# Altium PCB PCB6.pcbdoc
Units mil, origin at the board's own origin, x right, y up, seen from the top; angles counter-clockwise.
Board outline 8325 x 8105 mil, 2 copper layers (Top Layer, Bottom Layer); 35 components, 41 nets, 138 pads, 0 vias.
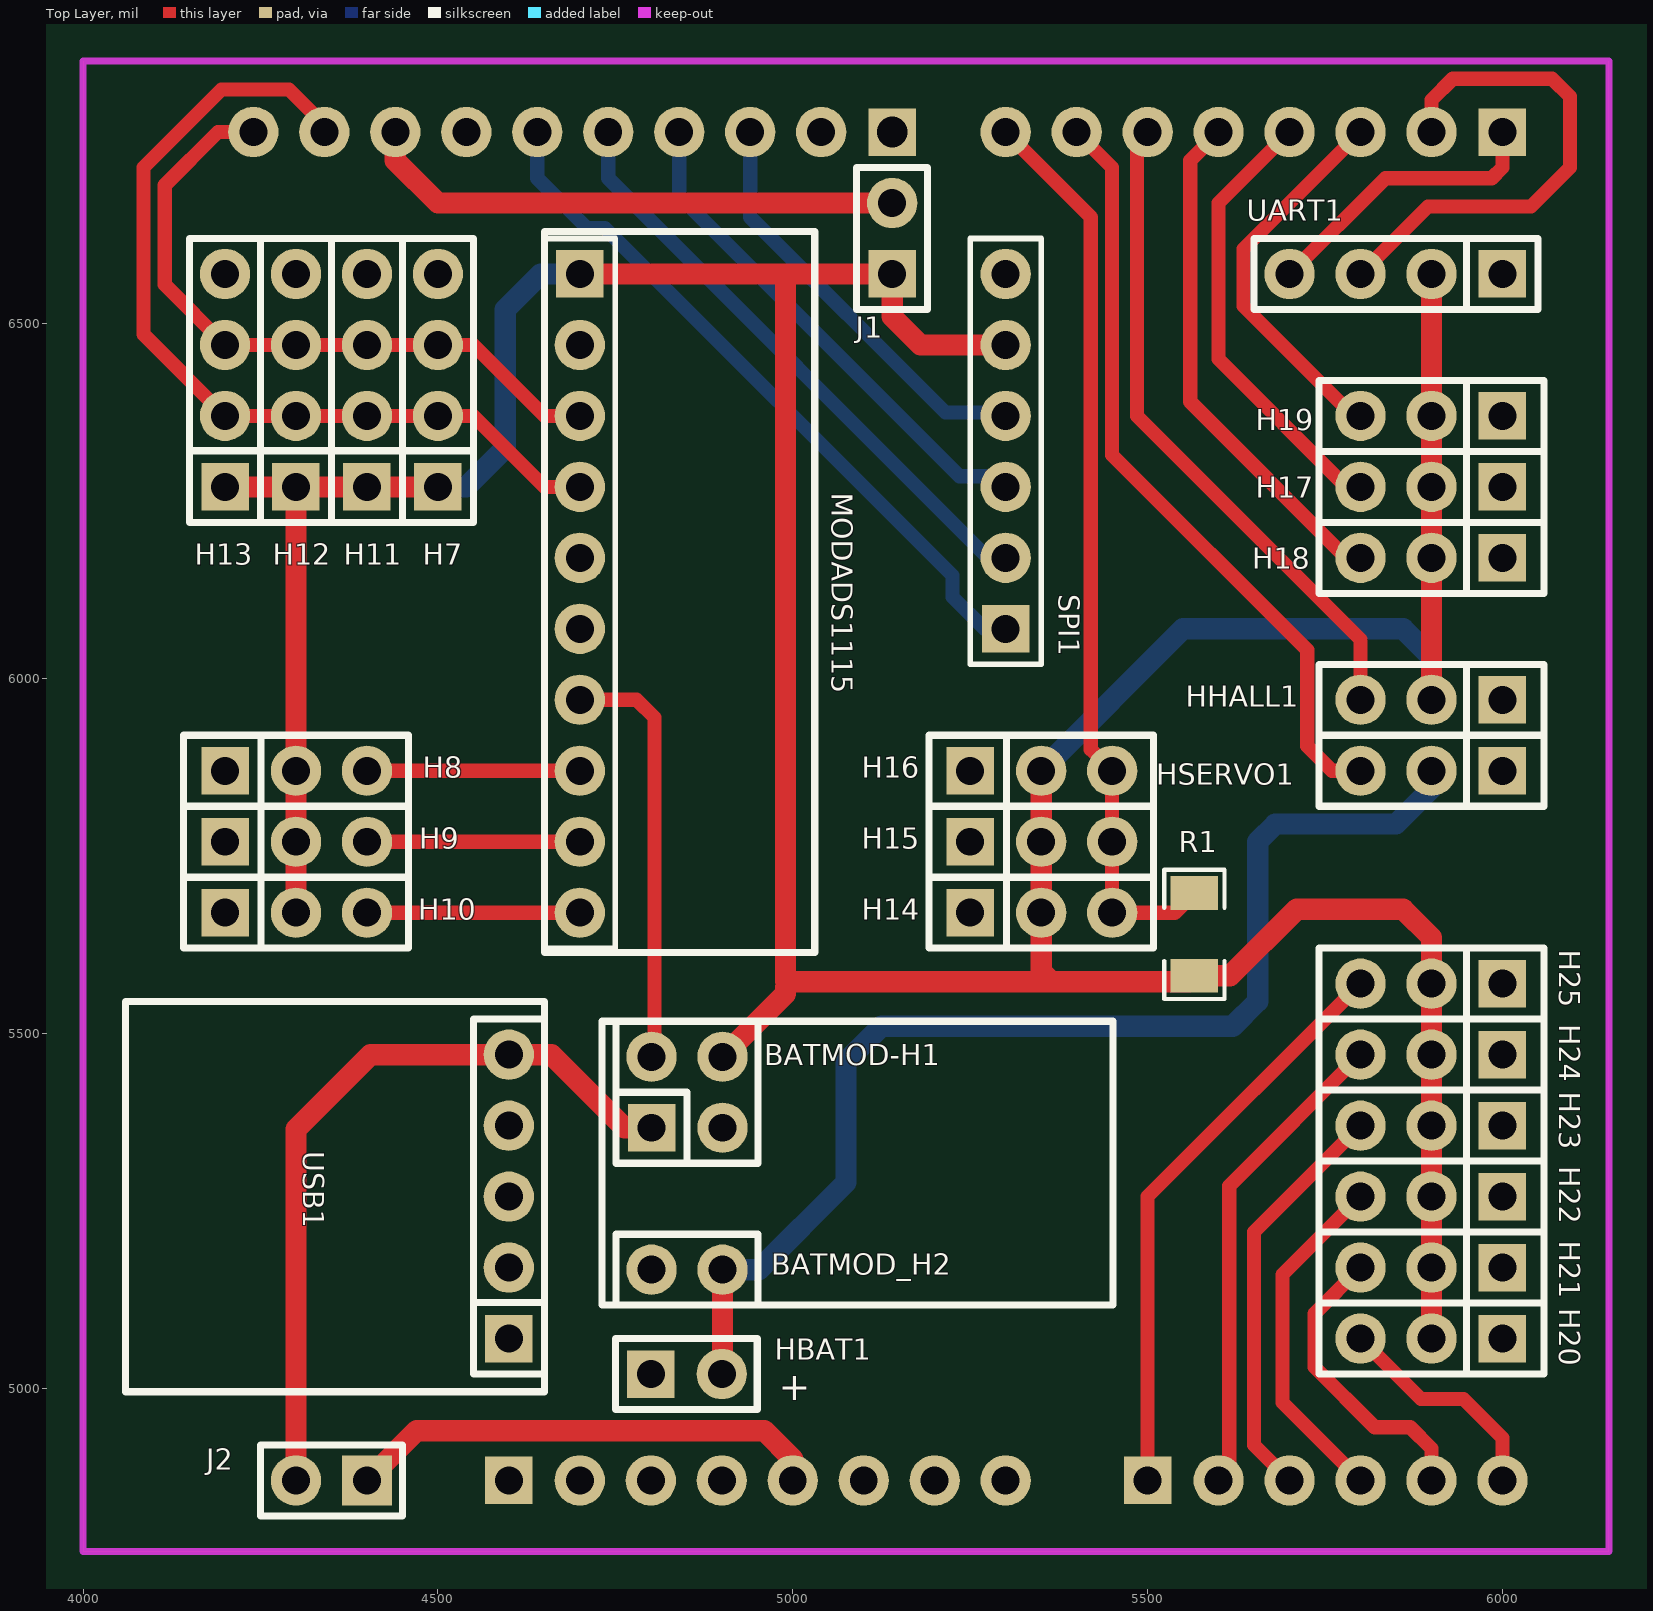
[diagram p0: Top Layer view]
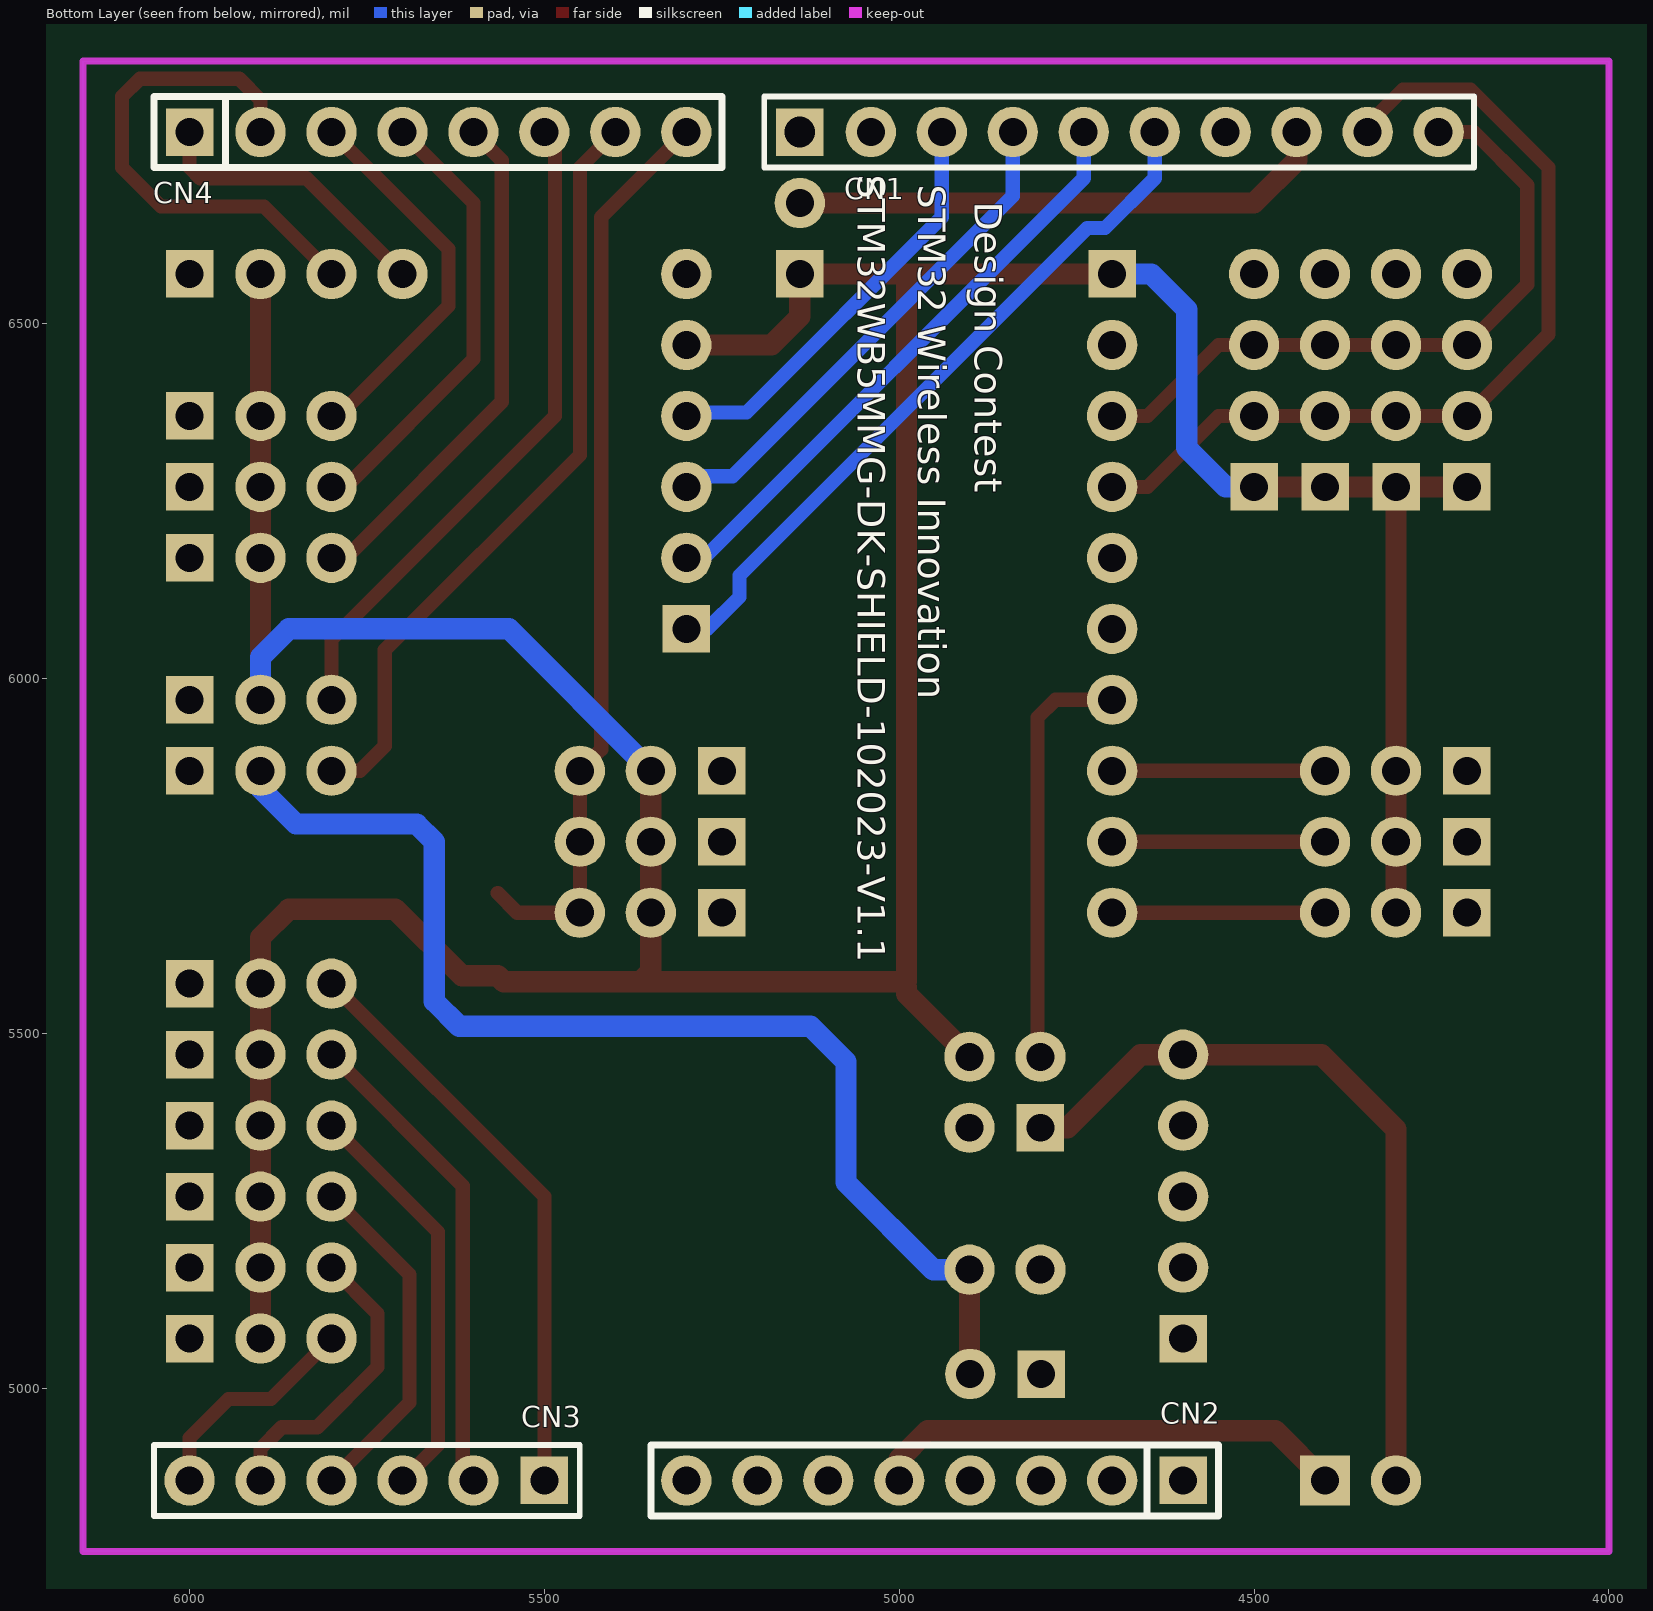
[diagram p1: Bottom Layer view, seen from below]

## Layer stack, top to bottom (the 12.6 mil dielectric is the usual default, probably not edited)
Top Layer: signal copper (thickness not stored)
Dielectric: dielectric 12.6, FR-4, Dk 4.8
Bottom Layer: signal copper (thickness not stored)

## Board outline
11075,2750 2750,2750 2750,10855 11075,10855

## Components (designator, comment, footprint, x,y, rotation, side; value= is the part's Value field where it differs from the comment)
BATMOD-H1 "HDR-M_2.54_2x2" hdr-th_4p-p2.54-v-m-r2-c2-s2.54-1 4851,5417 r0 top
BATMOD_H2 "HDR-M_2.54_1x2P" hdr-th_2p-p2.54-v-m-1#1 4851,5167 r0 top
CN1 "HDR-M_2.54_1x10P" hdr-th_10p-p2.54-v-m-1#1 4690,6770 r180 bottom
CN2 "HDR-M_2.54_1x8P" hdr-th_8p-p2.54-v-m#1 4950,4870 r0 bottom
CN3 "HDR-M_2.54_1x6P" hdr-th_6p-p2.54-v-m-1#1 5750,4870 r0 bottom
CN4 "HDR-M_2.54_1x8P" hdr-th_8p-p2.54-v-m#2 5650,6770 r180 bottom
H7 "HDR-M_2.54_1x4P" hdr-th_4p-p2.54-v-m 4500,6420 r90 top
H8 "HDR-M_2.54_1x3P" hdr-th_3p-p2.54-v-m#1 4300,5870 r0 top
H9 "HDR-M_2.54_1x3P" hdr-th_3p-p2.54-v-m#1 4300,5770 r0 top
H10 "HDR-M_2.54_1x3P" hdr-th_3p-p2.54-v-m#1 4300,5670 r0 top
H11 "HDR-M_2.54_1x4P" hdr-th_4p-p2.54-v-m 4400,6420 r90 top
H12 "HDR-M_2.54_1x4P" hdr-th_4p-p2.54-v-m 4300,6420 r90 top
H13 "HDR-M_2.54_1x4P" hdr-th_4p-p2.54-v-m 4200,6420 r90 top
H14 "HDR-M_2.54_1x3P" hdr-th_3p-p2.54-v-m#1 5350,5670 r0 top
H15 "HDR-M_2.54_1x3P" hdr-th_3p-p2.54-v-m#1 5350,5770 r0 top
H16 "HDR-M_2.54_1x3P" hdr-th_3p-p2.54-v-m#1 5350,5870 r0 top
H17 "HDR-M_2.54_1x3P" hdr-th_3p-p2.54-v-m#1 5900,6270 r180 top
H18 "HDR-M_2.54_1x3P" hdr-th_3p-p2.54-v-m#1 5900,6170 r180 top
H19 "HDR-M_2.54_1x3P" hdr-th_3p-p2.54-v-m#1 5900,6370 r180 top
H20 "HDR-M_2.54_1x3P" hdr-th_3p-p2.54-v-m#1 5900,5070 r180 top
H21 "HDR-M_2.54_1x3P" hdr-th_3p-p2.54-v-m#2 5900,5170 r180 top
H22 "HDR-M_2.54_1x3P" hdr-th_3p-p2.54-v-m#2 5900,5270 r180 top
H23 "HDR-M_2.54_1x3P" hdr-th_3p-p2.54-v-m#2 5900,5370 r180 top
H24 "HDR-M_2.54_1x3P" hdr-th_3p-p2.54-v-m#2 5900,5470 r180 top
H25 "HDR-M_2.54_1x3P" hdr-th_3p-p2.54-v-m#2 5900,5570 r180 top
HBAT1 "HDR-M_2.54_1x2P" hdr-th_2p-p2.54-v-m-1#2 4850,5020 r0 top
HHALL1 "HDR-M_2.54_1x3P" hdr-th_3p-p2.54-v-m#1 5900,5970 r180 top
HSERVO1 "HDR-M_2.54_1x3P" hdr-th_3p-p2.54-v-m#1 5900,5870 r180 top
J1 "HDR-M_2.54_1x2P" hdr-th_2p-p2.54-v-m-1#2 5140,6620 r90 top
J2 "HDR-M_2.54_1x2P" HDR-TH_2P-P2.54-V-M-1 4350,4870 r180 top
MODADS1115 "HDR-M_2.54_1x10P" hdr-th_10p-p2.54-v-m-1#2 4700,6120 r270 top
R1 "Res_1206" R1206 5565.77,5639.45 r270 top
SPI1 "HDR-M_2.54_1x6P" hdr-th_6p-p2.54-v-m-1#2 5300,6320 r90 top
UART1 "HDR-M_2.54_1x4P" hdr-th_4p-p2.54-v-m 5850,6570 r180 top
USB1 "HDR-M_2.54_1x5P" hdr-th_5p-p2.54-v-m 4600,5270 r90 top

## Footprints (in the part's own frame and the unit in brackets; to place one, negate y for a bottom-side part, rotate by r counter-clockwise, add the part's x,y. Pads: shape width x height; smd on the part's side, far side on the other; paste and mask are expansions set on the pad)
hdr-th_2p-p2.54-v-m-1#1 [mil]
  round 70.9 hole 39.4: 1(-50,0) 2(50,0)
  silkscreen extent -100,-50 100,50
hdr-th_2p-p2.54-v-m-1#2 [mil]
  rect 66.9x66.9 hole 39.4: 1(-50,0)
  round 70.9 hole 39.4: 2(50,0)
  silkscreen extent -100,-50 100,50
HDR-TH_2P-P2.54-V-M-1 [mm]
  rect 1.8x1.8 hole 1: 1(-1.27,0)
  round 1.8 hole 1: 2(1.27,0)
  silkscreen extent -2.54,-1.27 2.54,1.27
hdr-th_3p-p2.54-v-m#1 [mil]
  rect 66.9x66.9 hole 39.4: 1(-100,0)
  round 70.9 hole 39.4: 2(0,0) 3(100,0)
  silkscreen extent -158,-50 158,50
hdr-th_3p-p2.54-v-m#2 [mil]
  rect 66.93x66.93 hole 39.4: 1(-100,0)
  round 70.9 hole 39.4: 2(0,0) 3(100,0)
  silkscreen extent -158,-50 158,50
hdr-th_4p-p2.54-v-m [mil]
  rect 66.9x66.9 hole 39.4: 1(-150,0)
  round 70.9 hole 39.4: 2(-50,0) 3(50,0) 4(150,0)
  silkscreen extent -200,-50 200,50
hdr-th_4p-p2.54-v-m-r2-c2-s2.54-1 [mil]
  rect 66.9x66.9 hole 39.4: 1(-50,-50)
  round 70.9 hole 39.4: 2(-50,50) 3(50,-50) 4(50,50)
  silkscreen extent -100,-100 100,100
hdr-th_5p-p2.54-v-m [mil]
  rect 66.9x66.9 hole 39.4: 1(-200,0)
  round 70.9 hole 39.4: 2(-100,0) 3(0,0) 4(100,0) 5(200,0)
  silkscreen extent -250,-50 250,50
hdr-th_6p-p2.54-v-m-1#1 [mm]
  rect 1.699x1.699 hole 1.001: 1(-6.35,0)
  round 1.8 hole 1.001: 2(-3.81,0) 3(-1.27,0) 4(1.27,0) 5(3.81,0) 6(6.35,0)
  silkscreen extent -7.62,-1.27 7.62,1.27
hdr-th_6p-p2.54-v-m-1#2 [mm]
  rect 1.699x1.699 hole 1.001: 1(-6.35,0)
  round 1.801 hole 1.001: 2(-3.81,0) 3(-1.27,0) 4(1.27,0) 5(3.81,0) 6(6.35,0)
  silkscreen extent -7.62,-1.27 7.62,1.27
hdr-th_8p-p2.54-v-m#1 [mm]
  rect 1.699x1.699 hole 1.001: 1(-8.89,0)
  round 1.801 hole 1: 2(-6.35,0) 3(-3.81,0) 4(-1.27,0) 5(1.27,0) 6(3.81,0) 7(6.35,0) 8(8.89,0)
  silkscreen extent -10.16,-1.27 10.16,1.27
hdr-th_8p-p2.54-v-m#2 [mm]
  rect 1.699x1.699 hole 1: 1(-8.89,0)
  round 1.801 hole 1: 2(-6.35,0) 3(-3.81,0) 4(-1.27,0) 5(1.27,0) 6(3.81,0) 7(6.35,0) 8(8.89,0)
  silkscreen extent -10.16,-1.27 10.16,1.27
hdr-th_10p-p2.54-v-m-1#1 [mm]
  rect 1.699x1.7 hole 1.1: 1(-11.43,0)
  round 1.801 hole 1.001: 2(-8.89,0) 3(-6.35,0) 4(-3.81,0) 5(-1.27,0) 6(1.27,0) 7(3.81,0) 8(6.35,0) 9(8.89,0) 10(11.43,0)
  silkscreen extent -12.7,-1.27 12.7,1.27
hdr-th_10p-p2.54-v-m-1#2 [mm]
  rect 1.699x1.699 hole 1.001: 1(-11.43,0)
  round 1.801 hole 1.001: 2(-8.89,0) 3(-6.35,0) 4(-3.81,0) 5(-1.27,0) 6(1.27,0) 7(3.81,0) 8(6.35,0) 9(8.89,0) 10(11.43,0)
  silkscreen extent -12.7,-1.27 12.7,1.27
R1206 [mil]
  rect 47.54x66.97 smd: 1(-58.22,0) 2(58.22,0)
  silkscreen extent -91,-42 91,42

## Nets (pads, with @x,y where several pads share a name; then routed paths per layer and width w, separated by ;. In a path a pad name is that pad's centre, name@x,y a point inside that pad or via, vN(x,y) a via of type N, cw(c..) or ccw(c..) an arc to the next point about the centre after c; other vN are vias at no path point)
3V3: BATMOD-H1.4 H7.1 H8.2 H9.2 H10.2 H11.1 H12.1 H13.1 H14.2 H15.2 H16.2 H17.2 H18.2 H19.2 H20.2 H21.2 H22.2 H23.2 H24.2 H25.2 HHALL1.2 J1.1 MODADS1115.1 R1.2 SPI1.5 UART1.2 | length 6296.7
  Top Layer w30: H13.1 H12.1 ; H10.2 H9.2 H8.2 H12.1 ; H7.1 H11.1 H12.1 ; MODADS1115.1 4989.89,6570 ; BATMOD-H1.4 4989.89,5555.89 4989.89,5564.89 ; SPI1.5 5180,6470 5140,6510 J1.1 4989.89,6570 ; H16.2 H15.2 H14.2 5350,5586.99 5364.33,5572.67 ; H20.2 H21.2 H22.2 H23.2 H24.2 H25.2 5900,5635 5860,5675 5710,5675 5616.23,5581.23 R1.2 5557.21,5572.67 5364.33,5572.67 ; HHALL1.2 H18.2 H17.2 H19.2 UART1.2 ; 4989.89,6570 4989.89,5573 4993.95,5568.95 4997.67,5572.67 5364.33,5572.67
  Bottom Layer w30: H7.1 4540,6270 4595,6325 4595,6520 4645,6570 MODADS1115.1 ; H16.2 5550,6070 5860,6070 5900,6030 HHALL1.2
5V: CN2.5 J2.1 | length 675.6
  Top Layer w30: J2.1 4470,4940 4960,4940 5000,4900 CN2.5
AIN1: H8.3 MODADS1115.8 | length 300
  Top Layer w20: H8.3 MODADS1115.8
AIN2: H9.3 MODADS1115.9 | length 300
  Top Layer w20: H9.3 MODADS1115.9
AIN3: H10.3 MODADS1115.10 | length 300
  Top Layer w20: H10.3 MODADS1115.10
ALERT: MODADS1115.6
AVDD: CN1.8 J1.2 | length 764.9
  Top Layer w30: CN1.8 4440,6730 4500,6670 J1.2
D+: USB1.3
D-: USB1.4
GND: BATMOD-H1.3 BATMOD_H2.1 CN1.7 CN2.6 CN2.7 H7.4 H8.1 H9.1 H10.1 H11.4 H12.4 H13.4 H14.1 H15.1 H16.1 H17.1 H18.1 H19.1 H20.1 H21.1 H22.1 H23.1 H24.1 H25.1 HBAT1.1 HHALL1.1 HSERVO1.1 MODADS1115.2 MODADS1115.5 SPI1.6 UART1.1 USB1.1
IO: USB1.2
IOREF: CN2.2
NRST: CN2.3
PA1_SPI1_SCK: CN1.6 SPI1.1 | length 1005.6
  Bottom Layer w20: CN1.6 4640,6705 4710,6635 4735,6635 5225,6145 5225,6115 5270,6070 SPI1.1
PA2: CN3.2 H24.3 | length 682.8
  Top Layer w20: CN3.2 5615,4885 5615,5285 H24.3
PA4_SPI1_NSS: CN1.3 SPI1.4 | length 596
  Bottom Layer w20: CN1.3 4940,6650 5215,6375 5295,6375 SPI1.4
PA5: CN3.3 H23.3 | length 582.8
  Top Layer w20: CN3.3 5650,4920 5650,5220 H23.3
PA7_SPI1_MOSI/TIM17_CH1: CN1.4 SPI1.3 | length 719.8
  Bottom Layer w20: CN1.4 4840,6680 5235,6285 5285,6285 SPI1.3
PA10_I2C1_SDA: CN1.9 H7.2 H11.2 H12.2 H13.2 MODADS1115.4 | length 1270.3
  Top Layer w20: CN1.9 4340,6780 4290,6830 4195,6830 4085,6720 4085,6485 H13.2 H12.2 H11.2 H7.2 4550,6370 4650,6270 MODADS1115.4
PB2/ONEWIRE: CN4.8 H14.3 H15.3 H16.3 R1.1 | length 1289.4
  Top Layer w20: CN4.8 5420,6650 5420,5900 H16.3 H15.3 H14.3 5538.1,5670 R1.1
PB4_SPI1_MISO: CN1.5 SPI1.2 | length 846.6
  Bottom Layer w20: CN1.5 4740,6705 5275,6170 SPI1.2
PB5_LPUART1_TX: CN4.2 UART1.3 | length 719.9
  Top Layer w20: UART1.3 5895,6665 6040,6665 6095,6720 6095,6820 6070,6845 5930,6845 5900,6815 CN4.2
PB8_I2C1_SCL: CN1.10 H7.3 H11.3 H12.3 H13.3 MODADS1115.3 | length 957.7
  Top Layer w20: CN1.10 4190,6770 4115,6695 4115,6555 H13.3 H12.3 H11.3 H7.3 4550,6470 4650,6370 MODADS1115.3
PB10: CN4.6 HHALL1.3 | length 936.7
  Top Layer w20: CN4.6 5485,6755 5485,6370 5800,6055 HHALL1.3
PC0_LPUART1_RX: CN4.1 UART1.4 | length 412.1
  Top Layer w20: UART1.4 5835,6705 5985,6705 6000,6720 CN4.1
PC1: CN3.4 H22.3 | length 491.1
  Top Layer w20: CN3.4 5690,4980 5690,5160 H22.3
PC3: CN3.1 H25.3 | length 824.3
  Top Layer w20: CN3.1 5500,5270 H25.3
PC4: CN3.5 H21.3 | length 424.6
  Top Layer w20: H21.3 5735,5105 5735,5030 5820,4945 5870,4945 5900,4915 CN3.5
PC5: CN3.6 H20.3 | length 318
  Top Layer w20: H20.3 5885,4985 5945,4985 6000,4930 CN3.6
PD12_LPTIM2_IN1: CN4.3 H19.3 | length 542.5
  Top Layer w20: H19.3 5790,6370 5635,6525 5635,6605 CN4.3
PD13: CN1.1
PD14: CN4.4 H17.3 | length 636
  Top Layer w20: CN4.4 5600,6670 5600,6450 5780,6270 H17.3
PD15: CN1.2
PE0: CN4.7 HSERVO1.3 | length 1089.1
  Top Layer w20: CN4.7 5450,6720 5450,6315 5725,6040 5725,5905 5760,5870 HSERVO1.3
PE4: CN4.5 H18.3 | length 727.7
  Top Layer w20: CN4.5 5560,6730 5560,6390 5780,6170 H18.3
VBAT_IN: BATMOD_H2.2 HBAT1.2 HSERVO1.2 | length 1683.6
  Top Layer w30: HBAT1.2 4901,5021 BATMOD_H2.2
  Bottom Layer w30: BATMOD_H2.2 4952,5167 5075,5290 5075,5460 5125,5510 5620,5510 5655,5545 5655,5770 5680,5795 5850,5795 5900,5845 HSERVO1.2
VBUS: BATMOD-H1.1 J2.2 USB1.5 | length 1082.2
  Top Layer w30: J2.2 4300,5365 4405,5470 USB1.5 4660,5470 4763,5367 BATMOD-H1.1
VCC_STM: CN2.4
VIN: CN2.8
VSENS: BATMOD-H1.2 MODADS1115.7 | length 595
  Top Layer w20: MODADS1115.7 4780,5970 4805,5945 4805,5471 BATMOD-H1.2
"": CN2.1

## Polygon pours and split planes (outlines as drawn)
GND on Top Layer (solid, remove dead copper, pour order 0): 4000,4770 6150,4770 6150,6870 4000,6870
GND on Bottom Layer (solid, remove dead copper, pour order 1): 4000,4770 6150,4770 6150,6870 4000,6870

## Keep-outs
Board Outline Layer:
  lines w10 net "": 4000,4770 6150,4770 6150,6870 4000,6870 4000,4770

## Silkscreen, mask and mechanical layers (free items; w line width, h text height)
Top Silkscreen Layer:
  lines w10 net "": 4060,4995 4650,4995 4650,5545 4060,5545 4060,4995 ; 4650,5614 5031,5614 5031,6630 4650,6630 4650,5614 ; 4731,5117 5451,5117 5451,5517 4731,5517 4731,5117
  text "+" at 4980,4983.18 h39.22
Bottom Silkscreen Layer:
  text "STM32WB5MMG-DK-SHIELD-102023-V1.1" at 5058.32,6709.62 h38.94 r90
  text "STM32 Wireless Innovation" at 4973.32,6695.94 h38.94 r90
  text "Design Contest" at 4893.32,6672.13 h38.94 r90
Mech6:
  lines w10 net "": 4770,4985 4930,4985 4930,5055 4770,5055 4770,4985 ; 5105,6540 5175,6540 5175,6700 5105,6700 5105,6540
  text "I2C1 SCL /  I2C1 SDA /  AVDD /  GND /  SPI1 SCK /  SPI1 MISO /  SPI1 MOSI /  SPI1 CS /  PD15 /  PD13" at 5172.8,6813.31 h77.37 r90
  text "PB2 ONEWIRE /  PE0 /  PB10 /  PE4 /  PD14 /  PD12 LPTIM2 IN /  PB5 LPUART1 TX /  PC0 LPUART1 RX" at 6027.8,6784.89 h77.08 r90
  text "RX /  TX /  3V3 /  GND" at 6582.8,6675.21 h75.57 r90
  text "GND/GND/GND/GND /  SCL/SCL/SCL/SCL /  SDA/SDA/SDA/SDA /  3V3/3V3/3V3/3V3" at 2881.98,6237.2 h75.57
  text "GND /  3V3 /  SPI1 CS /  SPI1 MOSI /  SPI1 MISO /  SPI1 SCK" at 6116.72,6032.2 h76.58
  text "LPTIM2_IN1/3V3/GND /  PD14/3V3/GND /  PE4/3V3/GND /   /  PB10/3V3/GND /  PE0/VBAT/GND" at 7043.5,5852.2 h76.58
  text "GND/3V3/ONEWIRE /  GND/3V3/ONEWIRE /  GND/3V3/ONEWIRE" at 6059.61,5652.2 h74.53
  text "GND/3V3/AIN1 /  GND/3V3/AIN2 /  GND/3V3/AIN3" at 3172.6,5642.2 h74.53
  text "USB VBUS IN /   /   /   /  USB GND" at 3261.47,5042.2 h76.18
  text "PC3 / 3V3 /GND /  PA2 / 3V3 / GND /  PA5 REL01/3V3/GND /  PC1 REL02/3V3/GND /  PC4/3V3/GND /  PC5/VBATIN/GND" at 6032.19,5037.2 h76.58
  text "PC5 /  PC4 /  PC1 REL02 /  PA5 REL01 /  PA2 /  PC3" at 5467.2,4823.28 h76.58 r270
  text "VIN /  GND /  GND /  5V /  VCC STM /  NRST /  IOREF" at 4667.2,4806.84 h76.86 r270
